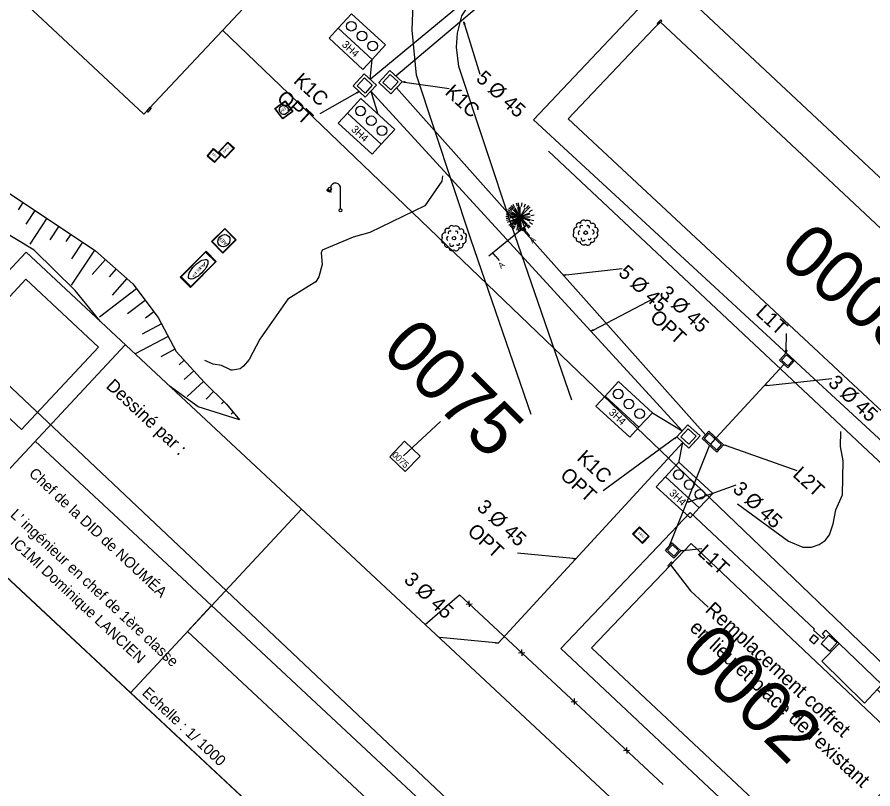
# Model space of a CAD drawing. Extents: x 343997 to 344255, y 298512 to 298767.
# Drawn here: x 344085.4 to 344145.1, y 298564.4 to 298618.2 of the extents above; entities that cross this region are included whole.
import ezdxf

# ---------------------------------------------------------------- set-up
doc = ezdxf.new("R2010")
doc.units = 0
for name, color, linetype in [('Commentaires', 7, 'Continuous'), ('Default', 7, 'Continuous'), ('DH_CADRE -CARTOUCHE', 7, 'Continuous'), ('DH_CADRE-CARTOUCHE', 7, 'Continuous'), ('DH_CADRE-CARTOUCHE-NORD', 7, 'Continuous'), ('DH_TEXTE', 7, 'Continuous'), ('DIR-Projet VRD1', 7, 'Continuous'), ('EDE - coupe BT', 7, 'Continuous'), ('EDE - VRD - O-DONNEE', 7, 'Continuous'), ('EL-coffret', 7, 'Continuous'), ('GO_DALLE', 7, 'Continuous'), ('O-Projet New VRD', 7, 'Continuous'), ('OPT chambre', 7, 'Continuous'), ('OPT texte', 7, 'Continuous'), ('OPT VRD', 7, 'Continuous'), ('PC_REBAR', 7, 'Continuous'), ('PS_HATCH', 7, 'Continuous'), ('PS_OBJECT', 7, 'Continuous'), ('PS_PLATE', 7, 'Continuous'), ('PS_WELD', 7, 'Continuous'), ('RES_EAU', 7, 'Continuous'), ('RES_ELECTRICITE', 7, 'Continuous'), ('RES_TELEPHONE SOUTERRAIN', 7, 'Continuous')]:
    doc.layers.add(name, color=color, linetype=linetype)

# ---------------------------------------------------------------- blocks, each defined once
blk = doc.blocks.new('RES_EAU')
at = {"layer": 'RES_EAU'}
for points in [[(0, 0), (0, 0.1), (0.1, 0.1), (0.1, 0)], [(0.0025, 0.0025), (0.0025, 0.0975), (0.0975, 0.0975), (0.0975, 0.0025)]]:
    blk.add_lwpolyline(points, close=True, dxfattribs=at)
blk.add_circle((0.05, 0.05), 0.035, dxfattribs=at)
blk.add_text('AEP', height=0.02, dxfattribs=at).set_placement((0.0224, 0.0448))
blk = doc.blocks.new('R3')
at = {"layer": 'Default'}
for p, q in [((0, 0.1), (0.1, 0.1)), ((0, 0), (0, 0.1)), ((0.1, 0.1), (0.1, 0)), ((0.1, 0), (0, 0))]:
    blk.add_line(p, q, dxfattribs=at)
blk = doc.blocks.new('RES_ELECTRICITE')
at = {"layer": 'RES_ELECTRICITE'}
for points in [[(0, 0), (0, 0.1), (0.1, 0.1), (0.1, 0)], [(0.005, 0.005), (0.005, 0.095), (0.095, 0.095), (0.095, 0.005)]]:
    blk.add_lwpolyline(points, close=True, dxfattribs=at)
blk.add_text('EEC', height=0.02, dxfattribs=at).set_placement((0.0237, 0.046))
blk = doc.blocks.new('EDF1')
at = {"layer": 'Default'}
for points in [[(-0.0855, 0.1462), (-0.0985, 0.1373)], [(-0.083, 0.1422), (-0.0931, 0.1303)], [(-0.0793, 0.1397), (-0.086, 0.1257)], [(-0.0753, 0.1388), (-0.0781, 0.1235)], [(-0.0701, 0.14), (-0.0684, 0.1241)], [(0, 0.01), (0, 0.15)]]:
    blk.add_lwpolyline(points, dxfattribs=at)
for centre, radius in [((-0.075, 0.15), 0.0112), ((0, 0), 0.01)]:
    blk.add_circle(centre, radius, dxfattribs=at)
blk.add_arc((-0.035, 0.155), 0.0354, 351.8699, 171.8699, dxfattribs=at)
blk = doc.blocks.new('ARB1')
at = {"layer": 'Default'}
blk.add_circle((0, 0), 0.0122, dxfattribs=at)
for centre, radius, start, end in [((-0.0471, 0.0503), 0.0183, 53.95544, 222.20655), ((-0.0153, 0.0664), 0.0211, 43.69255, 183.5969), ((0.0139, 0.0613), 0.0241, 358.45835, 125.19284), ((0.0501, 0.0468), 0.0183, 325.14445, 131.01755), ((-0.0613, 0.0139), 0.0241, 88.45835, 215.19284), ((-0.0373, -0.0024), 0.0149, 103.70924, 242.34652), ((-0.0276, 0.037), 0.0134, 52.43963, 209.54959), ((0.0164, 0.038), 0.0112, 330.58954, 133.71274), ((0.0458, 0.0052), 0.0137, 276.62143, 88.96702), ((0.0613, -0.0139), 0.0241, 268.45835, 35.19284), ((0.0664, 0.0153), 0.0211, 313.69255, 93.5969), ((-0.0664, -0.0153), 0.0211, 133.69255, 273.5969), ((-0.0478, -0.0443), 0.019, 155.22426, 300.93774), ((-0.0163, -0.042), 0.0148, 159.53711, 338.16632), ((0.0271, -0.038), 0.0112, 210.58954, 13.71274), ((0.0448, -0.0483), 0.0188, 243.13234, 33.02965), ((-0.0139, -0.0613), 0.0241, 178.45835, 305.19284), ((0.0153, -0.0664), 0.0211, 223.69255, 3.5969)]:
    blk.add_arc(centre, radius, start, end, dxfattribs=at)
blk = doc.blocks.new('ARB2')
at = {"layer": 'Default'}
for p, q in [((-0.0575, 0.0453), (-0.0775, 0.0605)), ((-0.0513, 0.0525), (-0.0688, 0.0702)), ((-0.0438, 0.0589), (-0.0588, 0.0786)), ((-0.0356, 0.0642), (-0.0481, 0.0858)), ((-0.0181, 0.0716), (-0.0244, 0.0956)), ((-0.0088, 0.0736), (-0.0119, 0.0983)), ((0.0106, 0.0736), (0.0144, 0.0983)), ((0.0287, 0.0684), (0.0388, 0.0914)), ((0.0456, 0.0589), (0.0612, 0.0786)), ((0.0531, 0.0525), (0.0706, 0.0702)), ((-0.0731, 0), (-0.0981, 0)), ((-0.0725, 0.01), (-0.0969, 0.0133)), ((-0.0706, 0.0195), (-0.0944, 0.0259)), ((-0.0675, 0.0286), (-0.09, 0.0381)), ((-0.0631, 0.0373), (-0.0844, 0.0497)), ((0.065, 0.0373), (0.0862, 0.0497)), ((0.0744, 0.01), (0.0987, 0.0133)), ((-0.0725, -0.01), (-0.0969, -0.0133)), ((-0.0706, -0.0195), (-0.0944, -0.0259)), ((-0.0675, -0.0287), (-0.09, -0.0383)), ((-0.0575, -0.0455), (-0.0775, -0.0605)), ((-0.0513, -0.0527), (-0.0688, -0.0702)), ((-0.0438, -0.0591), (-0.0588, -0.0787)), ((0.0456, -0.0591), (0.0612, -0.0787)), ((0.0531, -0.0527), (0.0706, -0.0702)), ((0.065, -0.0373), (0.0862, -0.0498)), ((0.0725, -0.0195), (0.0963, -0.0259)), ((-0.0356, -0.0644), (-0.0481, -0.0859)), ((-0.0181, -0.0717), (-0.0244, -0.0956)), ((-0.0088, -0.0737), (-0.0119, -0.0983)), ((0.0013, -0.0741), (0.0013, -0.0989)), ((0.0106, -0.0737), (0.0144, -0.0983)), ((0.02, -0.0717), (0.0263, -0.0956)), ((0.0287, -0.0686), (0.0388, -0.0916))]:
    blk.add_line(p, q, dxfattribs=at)
for points in [[(-0.0688, 0.0091), (0.0013, 0), (-0.0338, 0.0608)], [(-0.0169, 0.0677), (0.0013, 0), (-0.06, 0.035)], [(0.0013, 0.0008), (0.0013, 0), (-0.0081, 0.0695)], [(0.0362, 0.0608), (0.0013, 0), (0.0013, 0.0702)], [(-0.0487, -0.0497), (0.0013, 0), (-0.0694, 0)], [(-0.0638, -0.0269), (0.0013, 0), (-0.0688, -0.0092)], [(-0.0487, 0.0495), (0.0013, 0), (-0.0669, 0.0181)], [(-0.0419, 0.0556), (0.0013, 0), (-0.0638, 0.0269)], [(-0.0169, -0.0678), (0.0013, 0), (-0.06, -0.0352)], [(-0.0544, -0.0428), (0.0013, 0), (-0.0338, -0.0608)], [(-0.0081, -0.0695), (0.0013, 0), (-0.0419, -0.0558)], [(0.0013, -0.0702), (0.0013, 0), (0, 0)], [(0.0656, 0.0269), (0.0013, 0), (0.0506, 0.0495)], [(0.0688, 0.0181), (0.0013, 0), (0.0713, 0)], [(0.0438, -0.0558), (0.0013, 0), (0.0656, -0.0269)], [(0.0506, -0.0497), (0.0013, 0), (0.0688, -0.0181)], [(0.01, -0.0695), (0.0013, 0), (0.0281, -0.0648)], [(0.0019, 0), (0.0013, 0), (0.0013, -0.0009)]]:
    blk.add_lwpolyline(points, dxfattribs=at)
blk = doc.blocks.new('K1C')
at = {"layer": 'Default'}
for points in [[(35083.6085, 29821.5636), (35083.7239, 29821.5636), (35083.7239, 29821.6785), (35083.6085, 29821.6785)], [(35083.6287, 29821.6586), (35083.7037, 29821.6586), (35083.7037, 29821.5836), (35083.6287, 29821.5836)]]:
    blk.add_lwpolyline(points, close=True, dxfattribs=at)
for points in [[(35083.7037, 29821.6586), (35083.7039, 29821.6585)], [(35083.6085, 29821.5637), (35083.6087, 29821.5636)]]:
    blk.add_lwpolyline(points, dxfattribs=at)
blk = doc.blocks.new('_U58')
at = {"layer": 'EDE - VRD - O-DONNEE'}
for points in [[(0.01067, 0.01553), (-0.01067, 0.01553), (-0.01067, 0.00632), (0.01067, 0.00632)], [(-0.01067, 0.00632), (0.01067, 0.00632), (0.01067, 0), (-0.01067, 0)]]:
    blk.add_lwpolyline(points, close=True, dxfattribs=at)
for centre in [(-0.00689, 0.01114), (-0.00013, 0.01114), (0.00664, 0.01114)]:
    blk.add_circle(centre, 0.00225, dxfattribs=at)
blk.add_text('3H4', height=0.0035, dxfattribs=at).set_placement((-0.00426, 0.00143))

msp = doc.modelspace()

# ---------------------------------------------------------------- linework, layer by layer
at = {"layer": 'Commentaires'}
msp.add_lwpolyline([(344130.965, 298580.019), (344130.964, 298580.02), (344130.965, 298580.02)], close=True, dxfattribs=at)
for points in [[(344130.965, 298580.019), (344132.351, 298578.198)], [(344132.351, 298578.198), (344133.575, 298577.071)]]:
    msp.add_lwpolyline(points, dxfattribs=at)
at = {"layer": 'Default'}
msp.add_lwpolyline([(344111.955, 298613.702), (344111.956, 298613.7)], dxfattribs=at)
at = {"layer": 'DH_CADRE -CARTOUCHE'}
for p, q in [((344092.933, 298595.371), (344080.994, 298582.577)), ((344098.957, 298577.174), (344086.661, 298588.65)), ((344105.23, 298583.896), (344093.29, 298571.102))]:
    msp.add_line(p, q, dxfattribs=at)
for points in [[(343997.309, 298660.673), (344147.183, 298520.807), (344245.09, 298625.72), (344095.215, 298765.586)], [(344086.014, 298601.829), (344159.123, 298533.601), (344147.183, 298520.807), (344074.074, 298589.035)], [(344080.645, 298594.187), (344085.706, 298589.464), (344091.07, 298595.212), (344086.009, 298599.935)], [(344098.957, 298577.174), (344125.741, 298552.18), (344124.053, 298550.372), (344097.27, 298575.367)]]:
    msp.add_lwpolyline(points, close=True, dxfattribs=at)
at = {"layer": 'DH_CADRE-CARTOUCHE'}
for points in [[(344121.252, 298590.512), (344117.022, 298602.738), (344113.246, 298614.159), (344112.944, 298617.299), (344113.043, 298619.78), (344112.777, 298622.825), (344112.214, 298626.551), (344111.396, 298629.953)], [(344124.087, 298591.493), (344119.864, 298603.699), (344116.2, 298614.781), (344116.04, 298616.133), (344116.105, 298617.106), (344116.408, 298618.318), (344117.143, 298619.443), (344117.987, 298620.373), (344118.918, 298621.174), (344120.412, 298621.951)]]:
    msp.add_lwpolyline(points, dxfattribs=at)
at = {"layer": 'DH_CADRE-CARTOUCHE-NORD'}
msp.add_line((344099.715, 298617.296), (344158.902, 298560.479), dxfattribs=at)
msp.add_lwpolyline([(344122.446, 298608.863), (344157.538, 298575.936), (344158.902, 298560.479)], dxfattribs=at)
msp.add_lwpolyline([(344142.714, 298574.538), (344145.689, 298571.68), (344144.477, 298570.368), (344141.502, 298573.309)], close=True, dxfattribs=at)
at = {"layer": 'DH_TEXTE'}
msp.add_line((344112.348, 298587.62), (344114.924, 298590.008), dxfattribs=at)
at = {"layer": 'DIR-Projet VRD1'}
for p, q in [((344126.364, 298626.406), (344111.814, 298614.103)), ((344111.849, 298613.289), (344133.391, 298589.089)), ((344138.867, 298594.003), (344134.144, 298588.873)), ((344133.669, 298588.358), (344130.841, 298581.287))]:
    msp.add_line(p, q, dxfattribs=at)
at = {"layer": 'EDE - coupe BT'}
for p, q in [((344120.905, 298603.228), (344120.69, 298603.494)), ((344118.782, 298601.517), (344118.567, 298601.783))]:
    msp.add_line(p, q, dxfattribs=at)
for points in [[(344120.95, 298603.704), (344118.287, 298601.545)], [(344120.905, 298603.228), (344121.131, 298602.95)], [(344118.782, 298601.517), (344119.008, 298601.238)]]:
    msp.add_lwpolyline(points, dxfattribs=at)
at = {"layer": 'EL-coffret'}
for points in [[(344130.277, 298618.033), (344130.349, 298617.966), (344130.099, 298617.694), (344130.026, 298617.761)], [(344094.68, 298611.931), (344094.753, 298611.864), (344094.503, 298611.593), (344094.43, 298611.66)], [(344131.017, 298580.223), (344131.09, 298580.156), (344130.839, 298579.884), (344130.766, 298579.951)]]:
    msp.add_lwpolyline(points, close=True, dxfattribs=at)
at = {"layer": 'GO_DALLE'}
for points in [[(344173.444, 298593.641), (344172.427, 298592.568), (344178.462, 298586.939), (344174.396, 298582.587), (344168.376, 298588.228), (344167.085, 298586.853), (344168.386, 298585.586), (344159.324, 298576.069), (344121.411, 298611.054), (344130.716, 298620.945), (344149.461, 298603.379), (344147.717, 298601.519)], [(344145.36, 298571.324), (344150.236, 298566.706), (344141.289, 298557.281), (344123.303, 298574.184), (344132.335, 298583.661), (344140.996, 298575.54), (344140.93, 298575.464), (344141.582, 298574.891), (344141.725, 298575.026), (344141.55, 298575.188), (344141.782, 298575.465), (344142.714, 298574.538)]]:
    msp.add_lwpolyline(points, dxfattribs=at)
at = {"layer": 'O-Projet New VRD'}
for points in [[(344116.562, 298617.699), (344116.539, 298617.88), (344116.62, 298617.717)], [(344112.412, 298613.657), (344112.238, 298613.712), (344112.421, 298613.716)], [(344123.659, 298600.217), (344123.477, 298600.227), (344123.653, 298600.277)], [(344139.06, 298594.988), (344139.027, 298594.809), (344139, 298594.989)], [(344137.683, 298592.509), (344137.501, 298592.519), (344137.677, 298592.568)], [(344134.819, 298588.31), (344134.659, 298588.399), (344134.839, 298588.367)], [(344132.252, 298584.397), (344132.072, 298584.365), (344132.232, 298584.454)], [(344131.849, 298580.992), (344131.667, 298581.003), (344131.843, 298581.051)]]:
    msp.add_lwpolyline(points, close=True, dxfattribs=at)
for points in [[(344116.591, 298617.708), (344117.651, 298614.235)], [(344112.417, 298613.687), (344115.517, 298613.248)], [(344123.656, 298600.247), (344127.577, 298600.68)], [(344139.03, 298594.989), (344139.052, 298596.165)], [(344139.028, 298594.807), (344139.615, 298594.267), (344139.141, 298593.751), (344138.552, 298594.293), (344139.026, 298594.809)], [(344139.036, 298594.669), (344139.477, 298594.263), (344139.138, 298593.895), (344138.697, 298594.301), (344139.036, 298594.669)], [(344137.68, 298592.538), (344142.197, 298593.019)], [(344133.629, 298589.347), (344134.659, 298588.399), (344134.185, 298587.883), (344133.154, 298588.832), (344133.629, 298589.347)], [(344133.634, 298589.206), (344134.076, 298588.799), (344133.737, 298588.431), (344134.179, 298588.025), (344134.518, 298588.393), (344133.634, 298589.206), (344133.296, 298588.838), (344133.737, 298588.431)], [(344134.829, 298588.339), (344139.77, 298586.592)], [(344132.242, 298584.425), (344135.54, 298585.598)], [(344131.08, 298581.544), (344131.667, 298581.003), (344131.193, 298580.488), (344130.604, 298581.03), (344131.078, 298581.545)], [(344131.088, 298581.405), (344131.529, 298580.999), (344131.19, 298580.631), (344130.749, 298581.037), (344131.088, 298581.405)], [(344131.846, 298581.021), (344133.134, 298581.156)]]:
    msp.add_lwpolyline(points, dxfattribs=at)
at = {"layer": 'OPT chambre'}
for points in [[(344110.162, 298613.47), (344110.163, 298613.468)], [(344132.734, 298588.999), (344132.735, 298588.997)], [(344131.391, 298588.946), (344131.392, 298588.944)]]:
    msp.add_lwpolyline(points, dxfattribs=at)
at = {"layer": 'OPT texte'}
for points in [[(344110.021, 298613.871), (344110.143, 298615.27)], [(344109.086, 298612.937), (344106.506, 298611.478)], [(344110.056, 298613.057), (344110.548, 298611.46)], [(344125.571, 298596.396), (344129.864, 298598.641)], [(344129.691, 298590.632), (344131.78, 298589.368)], [(344131.246, 298588.838), (344126.261, 298585.173)], [(344131.536, 298587.132), (344131.815, 298588.554)], [(344124.172, 298580.464), (344120.289, 298580.833)], [(344118.759, 298574.584), (344114.876, 298574.953)]]:
    msp.add_lwpolyline(points, dxfattribs=at)
for points in [[(344109.071, 298612.963), (344109.242, 298613.025), (344109.1, 298612.911)], [(344125.584, 298596.37), (344125.411, 298596.313), (344125.557, 298596.423)], [(344131.228, 298588.863), (344131.391, 298588.945), (344131.264, 298588.814)], [(344124.175, 298580.494), (344124.352, 298580.447), (344124.169, 298580.434)], [(344118.762, 298574.614), (344118.938, 298574.567), (344118.756, 298574.554)]]:
    msp.add_lwpolyline(points, close=True, dxfattribs=at)
at = {"layer": 'OPT VRD'}
msp.add_line((344131.78, 298589.368), (344110.056, 298613.057), dxfattribs=at)
for points in [[(344122.894, 298624.526), (344110.021, 298613.871)], [(344131.815, 298588.554), (344118.938, 298574.567)]]:
    msp.add_lwpolyline(points, dxfattribs=at)
at = {"layer": 'PS_HATCH'}
for points in [[(344115.05, 298607.157), (344115.011, 298606.772), (344113.82, 298605.068), (344109.979, 298603.187), (344108.823, 298602.866), (344106.666, 298601.957), (344106.595, 298601.777), (344106.656, 298600.974), (344106.443, 298600.117), (344106.214, 298599.764), (344105.687, 298599.442), (344104.27, 298598.548), (344102.321, 298595.758), (344101.572, 298594.351), (344101.185, 298593.887), (344100.949, 298593.698), (344100.697, 298593.652), (344100.422, 298593.597), (344100.311, 298593.597), (344100.186, 298593.661), (344099.643, 298593.921), (344099.069, 298594.025), (344098.488, 298594.261)], [(344135.635, 298584.285), (344139.186, 298581.668), (344140.177, 298581.257), (344140.799, 298581.248), (344141.326, 298581.428), (344141.744, 298581.718), (344142.052, 298582.103), (344142.289, 298582.874), (344142.479, 298583.865), (344142.961, 298584.911), (344143.004, 298587.279), (344142.809, 298588.279), (344142.834, 298589.309)]]:
    msp.add_lwpolyline(points, dxfattribs=at)
at = {"layer": 'PS_OBJECT'}
for p, q in [((344085.795, 298605.289), (344085.464, 298604.788)), ((344086.63, 298604.738), (344086.003, 298603.789)), ((344087.464, 298604.186), (344086.27, 298602.39)), ((344088.297, 298603.632), (344087.668, 298602.687)), ((344089.13, 298603.078), (344088.799, 298602.58)), ((344089.963, 298602.524), (344089.188, 298601.36)), ((344090.795, 298601.97), (344089.165, 298599.518)), ((344091.551, 298601.316), (344090.625, 298600.272)), ((344092.299, 298600.653), (344091.812, 298600.103)), ((344093.048, 298599.989), (344092.02, 298598.831)), ((344093.73, 298599.264), (344091.131, 298597.297)), ((344094.333, 298598.466), (344093.102, 298597.534)), ((344094.937, 298597.669), (344094.354, 298597.227)), ((344095.471, 298596.827), (344094.107, 298596.109)), ((344095.937, 298595.942), (344093.625, 298594.726)), ((344096.402, 298595.056), (344095.41, 298594.534)), ((344097.039, 298594.291), (344096.685, 298593.969)), ((344097.712, 298593.551), (344097.042, 298592.941)), ((344098.385, 298592.811), (344097.241, 298591.771)), ((344099.095, 298592.106), (344098.581, 298591.584)), ((344099.808, 298591.405), (344099.649, 298591.243)), ((344100.474, 298590.659), (344100.317, 298590.526))]:
    msp.add_line(p, q, dxfattribs=at)
for points in [[(344071.223, 298615.847), (344074.994, 298612.914), (344080.628, 298608.697), (344087.004, 298604.491), (344090.87, 298601.921), (344093.455, 298599.627), (344095.237, 298597.273), (344096.484, 298594.901), (344098.438, 298592.752), (344100.001, 298591.216), (344100.912, 298590.144)], [(344091.183, 298597.005), (344089.452, 298599.151), (344086.594, 298601.972), (344083.865, 298603.59), (344080.978, 298604.751), (344078.857, 298606.454), (344076.588, 298608.919), (344075.058, 298610.502), (344071.223, 298615.847)], [(344100.912, 298590.144), (344098.025, 298591.038), (344096.004, 298592.505)]]:
    msp.add_lwpolyline(points, dxfattribs=at)
at = {"layer": 'PS_PLATE'}
msp.add_lwpolyline([(344092.72, 298634.812), (344105.192, 298623.148), (344094.238, 298611.445), (344080.101, 298624.659), (344082.365, 298627.121), (344084.042, 298625.579), (344092.72, 298634.812)], dxfattribs=at)
for points in [[(344159.085, 298578.25), (344123.824, 298611.129), (344130.237, 298617.899), (344165.405, 298584.943)], [(344113.5, 298587.607), (344112.411, 298588.638), (344111.376, 298587.552), (344112.465, 298586.521)], [(344125.459, 298574.243), (344141.227, 298559.424), (344148.086, 298566.649), (344132.39, 298581.516)]]:
    msp.add_lwpolyline(points, close=True, dxfattribs=at)
at = {"layer": 'PS_WELD'}
for p, q in [((344116.701, 298577.285), (344117.125, 298577.302)), ((344116.905, 298577.505), (344116.921, 298577.082)), ((344120.571, 298574.105), (344120.586, 298573.681)), ((344120.367, 298573.885), (344120.791, 298573.901)), ((344124.231, 298570.698), (344124.246, 298570.274)), ((344124.026, 298570.478), (344124.45, 298570.493)), ((344127.685, 298567.071), (344128.109, 298567.086)), ((344127.89, 298567.29), (344127.905, 298566.866))]:
    msp.add_line(p, q, dxfattribs=at)
msp.add_lwpolyline([(344113.851, 298575.85), (344116.239, 298577.918), (344119.964, 298574.466), (344130.452, 298564.699)], dxfattribs=at)
at = {"layer": 'RES_TELEPHONE SOUTERRAIN'}
msp.add_lwpolyline([(344006.37, 298666.609), (344159.504, 298522.019), (344160.824, 298520.82), (344163.6, 298518.226)], dxfattribs=at)

# ---------------------------------------------------------------- block references
at = {"layer": 'DH_CADRE-CARTOUCHE-NORD'}
for p, xscale, yscale, rotation in [((344140.642, 298574.781), 4.68412799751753, -4.4371612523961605, 50.82264), ((344142.039, 298574.001), 8.00529956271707, 7.74033504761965, 47.75372999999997)]:
    msp.add_blockref('R3', p, dxfattribs=dict(at, xscale=xscale, yscale=yscale, rotation=rotation))
at = {"layer": 'O-Projet New VRD', "xscale": 10, "yscale": 10, "rotation": -42.63277399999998}
msp.add_blockref('K1C', (-115983.46, 316833.685), dxfattribs=at)
at = {"layer": 'OPT chambre', "xscale": 10, "yscale": 10, "rotation": -42.63277399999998}
for p in [(-115985.253, 316833.453), (-115962.68, 316808.982)]:
    msp.add_blockref('K1C', p, dxfattribs=at)
at = {"layer": 'OPT texte', "xscale": 150, "yscale": 150, "rotation": -42.63277399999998}
for p in [(344108.323, 298615.656), (344108.97, 298609.745), (344126.936, 298590.002), (344131.143, 298584.376)]:
    msp.add_blockref('_U58', p, dxfattribs=at)
at = {"layer": 'PC_REBAR', "xscale": 10, "yscale": 10}
for name, p in [('ARB2', (344120.465, 298604.286)), ('ARB1', (344125.037, 298603.184)), ('ARB1', (344115.863, 298602.801))]:
    msp.add_blockref(name, p, dxfattribs=at)
at = {"layer": 'RES_EAU'}
for p, xscale, yscale, rotation in [((344103.912, 298611.113), 8.80750421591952, 9.18778627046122, 36.23525999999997), ((344100.674, 298602.688), 11.26591828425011, 13.087869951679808, 134.82486), ((344098.569, 298601.894), 25.569777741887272, 10.073602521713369, -134.87472000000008)]:
    msp.add_blockref('RES_EAU', p, dxfattribs=dict(at, xscale=xscale, yscale=yscale, rotation=rotation))
at = {"layer": 'RES_ELECTRICITE'}
for p, xscale, yscale, rotation in [((344099.871, 298608.378), 9.693433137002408, 6.171012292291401, 46.150708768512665), ((344098.642, 298608.528), 6.8986934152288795, 6.90076972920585, -41.04656495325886), ((344128.317, 298582.175), 9.52481702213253, 6.8580018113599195, -44.14338)]:
    msp.add_blockref('RES_ELECTRICITE', p, dxfattribs=dict(at, xscale=xscale, yscale=yscale, rotation=rotation))
at = {"layer": 'RES_ELECTRICITE', "xscale": 10, "yscale": 10}
msp.add_blockref('EDF1', (344107.946, 298604.744), dxfattribs=at)

# ---------------------------------------------------------------- texts
at = {"layer": 'Commentaires'}
for s, p in [('Remplacement coffret', (344133.311, 298576.799)), ("en lieu et place de l'existant", (344132.226, 298575.533))]:
    msp.add_text(s, height=1.00027, rotation=317.36723, dxfattribs=at).set_placement(p)
at = {"layer": 'DH_CADRE -CARTOUCHE'}
for s, height, p in [('Dessiné par :', 0.9, (344091.534, 298592.422)), ('Chef de la DID de NOUMÉA ', 0.75, (344086.164, 298586.311)), ("L' ingénieur en chef de 1ère classe", 0.75, (344084.87, 298583.441)), ('IC1MI Dominique LANCIEN', 0.75, (344084.866, 298581.532)), ('Echelle : 1/ 1000', 0.75, (344094.056, 298571.024))]:
    msp.add_text(s, height=height, rotation=316.97842, dxfattribs=at).set_placement(p)
at = {"layer": 'DH_TEXTE'}
for s, height, rotation, p in [('0003', 3.662, 320.36653, (344138.412, 298601.304)), ('0075', 3.662, 315.36654, (344110.698, 298594.891)), ('0075', 0.4452, 315.36654, (344111.505, 298587.655)), ('0002', 3.662, 315.36654, (344131.489, 298573.614))]:
    msp.add_text(s, height=height, rotation=rotation, dxfattribs=at).set_placement(p)
at = {"layer": 'EDE - coupe BT'}
for p in [(344121.32, 298602.4), (344119.141, 298600.644)]:
    msp.add_text('A', height=0.42, rotation=39.04276, dxfattribs=at).set_placement(p)
at = {"layer": 'O-Projet New VRD'}
for s, p in [('5 Ø 45', (344117.335, 298613.851)), ('K1C', (344115.168, 298612.889)), ('5 Ø 45', (344127.261, 298600.296)), ('L1T', (344136.839, 298597.52)), ('3 Ø 45', (344141.888, 298592.628)), ('L2T', (344139.417, 298586.234)), ('3 Ø 45', (344135.232, 298585.208)), ('L1T', (344132.782, 298580.798))]:
    msp.add_text(s, height=1.0003, rotation=317.36723, dxfattribs=at).set_placement(p)
at = {"layer": 'OPT texte'}
for s, p in [('K1C', (344104.608, 298613.69)), ('OPT', (344103.439, 298612.477)), ('3 Ø 45', (344130.113, 298598.856)), ('OPT', (344129.451, 298597.176)), ('K1C', (344124.362, 298587.386)), ('OPT', (344123.194, 298586.173)), ('3 Ø 45', (344117.389, 298583.947)), ('OPT', (344116.726, 298582.267)), ('3 Ø 45', (344112.306, 298578.895))]:
    msp.add_text(s, height=1.0003, rotation=317.36723, dxfattribs=at).set_placement(p)

doc.saveas('drawing.dxf')
